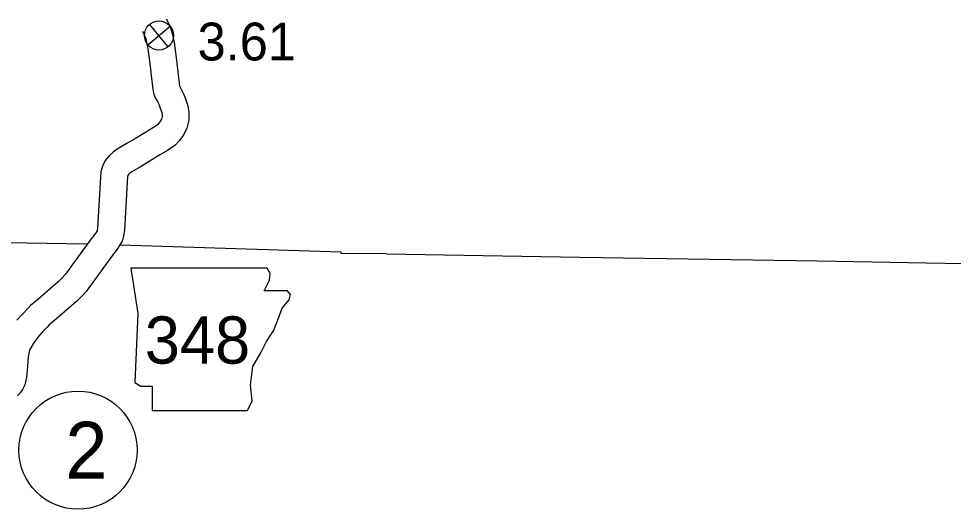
# Model space of a CAD drawing. Extents: x -939622 to -934245, y 1383184 to 1385301.
# Drawn here: x -936322.99 to -936291.65, y 1384704.85 to 1384721.28 of the extents above; entities that cross this region are included whole.
import ezdxf

# ---------------------------------------------------------------- set-up
doc = ezdxf.new("R2010")
doc.units = 0
for name, color, linetype in [('Level 11', 7, 'Continuous'), ('Level 21', 7, 'Continuous'), ('Level 25', 7, 'Continuous'), ('Level 26', 7, 'Continuous'), ('Level 27', 7, 'Continuous'), ('Level 8', 7, 'Continuous')]:
    doc.layers.add(name, color=color, linetype=linetype)

msp = doc.modelspace()

# ---------------------------------------------------------------- linework, layer by layer
at = {"layer": 'Level 11'}
for points in [[(-936318.041, 1384721.282), (-936317.95, 1384721.107), (-936317.867, 1384720.875), (-936317.821, 1384720.69), (-936317.781, 1384720.488), (-936317.733, 1384720.149), (-936317.688, 1384719.79), (-936317.657, 1384719.49), (-936317.608, 1384719.133), (-936317.593, 1384719.02), (-936317.591, 1384719.016), (-936317.551, 1384718.943), (-936317.463, 1384718.763), (-936317.395, 1384718.597), (-936317.322, 1384718.365), (-936317.28, 1384718.157), (-936317.281, 1384717.885), (-936317.35, 1384717.619), (-936317.449, 1384717.4), (-936317.594, 1384717.203), (-936317.74, 1384717.048), (-936317.887, 1384716.942), (-936318.001, 1384716.873), (-936318.287, 1384716.697), (-936318.61, 1384716.494), (-936318.906, 1384716.322), (-936319.195, 1384716.153), (-936319.261, 1384716.105), (-936319.304, 1384716.067), (-936319.333, 1384716.032), (-936319.343, 1384716.011)], [(-936318.84, 1384720.87), (-936318.777, 1384720.747), (-936318.73, 1384720.614), (-936318.7, 1384720.494), (-936318.669, 1384720.337), (-936318.625, 1384720.03), (-936318.582, 1384719.688), (-936318.551, 1384719.383), (-936318.5, 1384719.009), (-936318.469, 1384718.793), (-936318.409, 1384718.636), (-936318.351, 1384718.529), (-936318.284, 1384718.393), (-936318.242, 1384718.291), (-936318.195, 1384718.141), (-936318.18, 1384718.067), (-936318.18, 1384718.003), (-936318.202, 1384717.92), (-936318.231, 1384717.856), (-936318.286, 1384717.78), (-936318.335, 1384717.728), (-936318.384, 1384717.693), (-936318.471, 1384717.64), (-936318.762, 1384717.461), (-936319.074, 1384717.265), (-936319.36, 1384717.099), (-936319.689, 1384716.907), (-936319.825, 1384716.807), (-936319.954, 1384716.693), (-936320.09, 1384716.528), (-936320.184, 1384716.344), (-936320.239, 1384716.154)], [(-936320.239, 1384716.154), (-936320.343, 1384714.28), (-936320.355, 1384714.206), (-936320.363, 1384714.177), (-936320.38, 1384714.145), (-936320.402, 1384714.108), (-936320.588, 1384713.861), (-936321.417, 1384712.72), (-936321.526, 1384712.603), (-936321.66, 1384712.469), (-936322.441, 1384711.799), (-936322.578, 1384711.683), (-936322.685, 1384711.575), (-936322.86, 1384711.389), (-936323.048, 1384711.181)], [(-936319.345, 1384716.013), (-936319.447, 1384714.184), (-936319.474, 1384714.011), (-936319.524, 1384713.836), (-936319.595, 1384713.705), (-936319.65, 1384713.609), (-936319.865, 1384713.325), (-936320.722, 1384712.145), (-936320.879, 1384711.977), (-936321.048, 1384711.809), (-936321.858, 1384711.114), (-936321.965, 1384711.024), (-936322.036, 1384710.951), (-936322.199, 1384710.779), (-936322.349, 1384710.612), (-936322.43, 1384710.502), (-936322.507, 1384710.392), (-936322.587, 1384710.258), (-936322.616, 1384710.203), (-936322.626, 1384710.176), (-936322.648, 1384710.084), (-936322.668, 1384709.961), (-936322.696, 1384709.627), (-936322.732, 1384709.271), (-936322.787, 1384709.015), (-936322.863, 1384708.866), (-936322.941, 1384708.746), (-936323.03, 1384708.645)]]:
    msp.add_lwpolyline(points, dxfattribs=at)
at = {"layer": 'Level 21'}
msp.add_lwpolyline([(-936319.227, 1384712.928), (-936318.998, 1384711.405), (-936319.1, 1384709.096), (-936318.897, 1384708.969), (-936318.516, 1384708.969), (-936318.516, 1384708.157), (-936315.319, 1384708.157), (-936315.166, 1384708.487), (-936315.217, 1384709.02), (-936315.141, 1384709.629), (-936314.862, 1384710.111), (-936314.684, 1384710.466), (-936314.43, 1384710.847), (-936314.278, 1384711.253), (-936314.151, 1384711.583), (-936313.923, 1384711.862), (-936313.872, 1384712.04), (-936313.974, 1384712.167), (-936314.76, 1384712.167), (-936314.583, 1384712.522), (-936314.557, 1384712.75), (-936314.663, 1384712.926)], close=True, dxfattribs=at)
at = {"layer": 'Level 26'}
for p, q in [((-936318.663, 1384720.409), (-936317.911, 1384721.032)), ((-936317.976, 1384720.344), (-936318.598, 1384721.097))]:
    msp.add_line(p, q, dxfattribs=at)
msp.add_circle((-936318.287, 1384720.721), 0.488, dxfattribs=at)
at = {"layer": 'Level 27'}
msp.add_circle((-936321, 1384706.83), 1.98, dxfattribs=at)
at = {"layer": 'Level 8'}
for points in [[(-936320.713, 1384713.726), (-936328.079, 1384713.854)], [(-936312.172, 1384713.467), (-936319.583, 1384713.699)], [(-936312.173, 1384713.418), (-936312.172, 1384713.467)], [(-936310.654, 1384713.404), (-936312.173, 1384713.418)], [(-936310.654, 1384713.404), (-936304.177, 1384713.293), (-936296.207, 1384713.175), (-936288.283, 1384713.03)]]:
    msp.add_lwpolyline(points, dxfattribs=at)

# ---------------------------------------------------------------- texts
at = {"layer": 'Level 21'}
msp.add_text('348', height=1.584, dxfattribs=at).set_placement((-936318.762, 1384709.727))
at = {"layer": 'Level 25'}
msp.add_text('3.61', height=1.2672, dxfattribs=at).set_placement((-936316.991, 1384719.884))
at = {"layer": 'Level 27'}
msp.add_text('2', height=1.901, dxfattribs=at).set_placement((-936321.425, 1384705.879))

doc.saveas('drawing.dxf')
